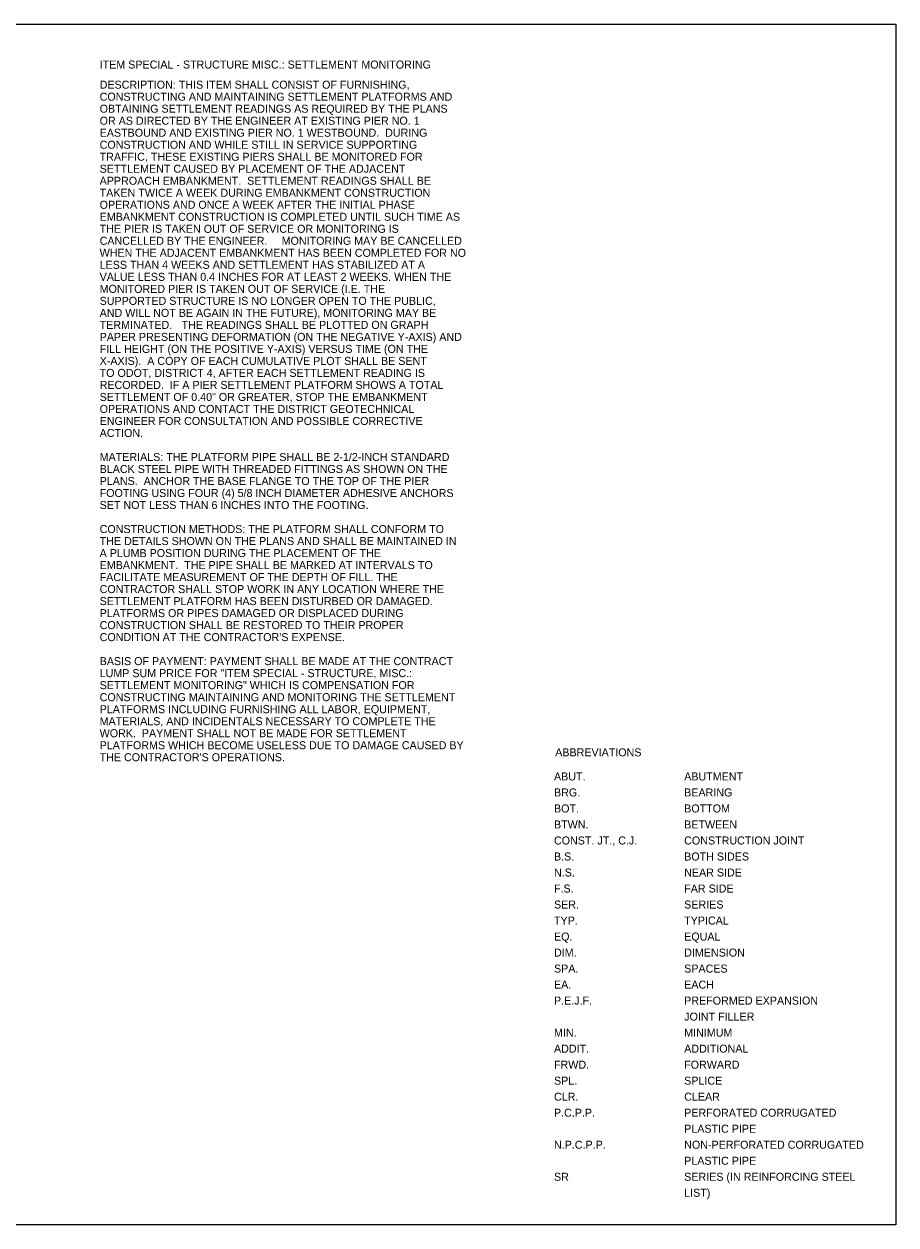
# Model space of a CAD drawing. Extents: x 1530552 to 1530730, y 675304 to 675366.
# Drawn here: x 1530669.97 to 1530685.22, y 675345.2 to 675366.2 of the extents above; entities that cross this region are included whole.
import ezdxf

# ---------------------------------------------------------------- set-up
doc = ezdxf.new("R2010")
doc.units = 0
doc.layers.add('BR_P_Gen_Text', color=7, linetype='Continuous')
doc.layers.add('Default', color=7, linetype='Continuous')

msp = doc.modelspace()

# ---------------------------------------------------------------- linework, layer by layer
at = {"layer": 'BR_P_Gen_Text'}
msp.add_lwpolyline([(1530654.722, 675366.197), (1530685.222, 675366.197), (1530685.222, 675345.197), (1530654.722, 675345.197)], close=True, dxfattribs=at)

# ---------------------------------------------------------------- texts
for s, p in [('ITEM SPECIAL - STRUCTURE MISC.: SETTLEMENT MONITORING', (1530671.295, 675365.418)), ('DESCRIPTION: THIS ITEM SHALL CONSIST OF FURNISHING, ', (1530671.295, 675365.066)), ('CONSTRUCTING AND MAINTAINING SETTLEMENT PLATFORMS AND ', (1530671.295, 675364.856)), ('OBTAINING SETTLEMENT READINGS AS REQUIRED BY THE PLANS ', (1530671.295, 675364.646)), ('OR AS DIRECTED BY THE ENGINEER AT EXISTING PIER NO. 1 ', (1530671.295, 675364.436)), ('EASTBOUND AND EXISTING PIER NO. 1 WESTBOUND.  DURING ', (1530671.295, 675364.226)), ('CONSTRUCTION AND WHILE STILL IN SERVICE SUPPORTING ', (1530671.295, 675364.016)), ('TRAFFIC, THESE EXISTING PIERS SHALL BE MONITORED FOR ', (1530671.295, 675363.806)), ('SETTLEMENT CAUSED BY PLACEMENT OF THE ADJACENT ', (1530671.295, 675363.596)), ('APPROACH EMBANKMENT.  SETTLEMENT READINGS SHALL BE ', (1530671.295, 675363.386)), ('TAKEN TWICE A WEEK DURING EMBANKMENT CONSTRUCTION ', (1530671.295, 675363.176)), ('OPERATIONS AND ONCE A WEEK AFTER THE INITIAL PHASE ', (1530671.295, 675362.966)), ('EMBANKMENT CONSTRUCTION IS COMPLETED UNTIL SUCH TIME AS ', (1530671.295, 675362.756)), ('THE PIER IS TAKEN OUT OF SERVICE OR MONITORING IS ', (1530671.295, 675362.546)), ('CANCELLED BY THE ENGINEER. ', (1530671.295, 675362.336)), ('MONITORING MAY BE CANCELLED ', (1530674.478, 675362.336)), ('WHEN THE ADJACENT EMBANKMENT HAS BEEN COMPLETED FOR NO ', (1530671.295, 675362.126)), ('LESS THAN 4 WEEKS AND SETTLEMENT HAS STABILIZED AT A ', (1530671.295, 675361.916)), ('VALUE LESS THAN 0.4 INCHES FOR AT LEAST 2 WEEKS. WHEN THE ', (1530671.295, 675361.706)), ('MONITORED PIER IS TAKEN OUT OF SERVICE (I.E. THE ', (1530671.295, 675361.496)), ('SUPPORTED STRUCTURE IS NO LONGER OPEN TO THE PUBLIC, ', (1530671.295, 675361.286)), ('AND WILL NOT BE AGAIN IN THE FUTURE), MONITORING MAY BE ', (1530671.295, 675361.076)), ('TERMINATED.', (1530671.295, 675360.866)), ('  THE READINGS SHALL BE PLOTTED ON GRAPH ', (1530672.624, 675360.866)), ('PAPER PRESENTING DEFORMATION (ON THE NEGATIVE Y-AXIS) AND ', (1530671.295, 675360.656)), ('FILL HEIGHT (ON THE POSITIVE Y-AXIS) VERSUS TIME (ON THE ', (1530671.295, 675360.446)), ('X-AXIS).  A COPY OF EACH CUMULATIVE PLOT SHALL BE SENT ', (1530671.295, 675360.236)), ('TO ODOT, DISTRICT 4, AFTER EACH SETTLEMENT READING IS ', (1530671.295, 675360.026)), ('RECORDED.  IF A PIER SETTLEMENT PLATFORM SHOWS A TOTAL ', (1530671.295, 675359.816)), ('SETTLEMENT OF 0.40" OR GREATER, STOP THE EMBANKMENT ', (1530671.295, 675359.606)), ('OPERATIONS AND CONTACT THE DISTRICT GEOTECHNICAL ', (1530671.295, 675359.396)), ('ENGINEER FOR CONSULTATION AND POSSIBLE CORRECTIVE ', (1530671.295, 675359.186)), ('ACTION.', (1530671.295, 675358.976)), ('MATERIALS: THE PLATFORM PIPE SHALL BE 2-1/2-INCH STANDARD ', (1530671.295, 675358.556)), ('BLACK STEEL PIPE WITH THREADED FITTINGS AS SHOWN ON THE ', (1530671.295, 675358.346)), ('PLANS.  ANCHOR THE BASE FLANGE TO THE TOP OF THE PIER ', (1530671.295, 675358.136)), ('FOOTING USING FOUR (4) 5/8 INCH DIAMETER ADHESIVE ANCHORS ', (1530671.295, 675357.926)), ('SET NOT LESS THAN 6 INCHES INTO THE FOOTING.', (1530671.295, 675357.716)), ('CONSTRUCTION METHODS: THE PLATFORM SHALL CONFORM TO ', (1530671.295, 675357.296)), ('THE DETAILS SHOWN ON THE PLANS AND SHALL BE MAINTAINED IN ', (1530671.295, 675357.086)), ('A PLUMB POSITION DURING THE PLACEMENT OF THE ', (1530671.295, 675356.876)), ('EMBANKMENT.  THE PIPE SHALL BE MARKED AT INTERVALS TO ', (1530671.295, 675356.666)), ('FACILITATE MEASUREMENT OF THE DEPTH OF FILL. THE ', (1530671.295, 675356.456)), ('CONTRACTOR SHALL STOP WORK IN ANY LOCATION WHERE THE ', (1530671.295, 675356.246)), ('SETTLEMENT PLATFORM HAS BEEN DISTURBED OR DAMAGED. ', (1530671.295, 675356.036)), ('PLATFORMS OR PIPES DAMAGED OR DISPLACED DURING ', (1530671.295, 675355.826)), ('CONSTRUCTION SHALL BE RESTORED TO THEIR PROPER ', (1530671.295, 675355.616)), ("CONDITION AT THE CONTRACTOR'S EXPENSE.", (1530671.295, 675355.406)), ('BASIS OF PAYMENT: PAYMENT SHALL BE MADE AT THE CONTRACT ', (1530671.295, 675354.986)), ('LUMP SUM PRICE FOR "ITEM SPECIAL - STRUCTURE, MISC.:  ', (1530671.295, 675354.776)), ('SETTLEMENT MONITORING" WHICH IS COMPENSATION FOR ', (1530671.295, 675354.566)), ('CONSTRUCTING MAINTAINING AND MONITORING THE SETTLEMENT ', (1530671.295, 675354.356)), ('PLATFORMS INCLUDING FURNISHING ALL LABOR, EQUIPMENT, ', (1530671.295, 675354.146)), ('MATERIALS, AND INCIDENTALS NECESSARY TO COMPLETE THE ', (1530671.295, 675353.936)), ('WORK.  PAYMENT SHALL NOT BE MADE FOR SETTLEMENT ', (1530671.295, 675353.726)), ('PLATFORMS WHICH BECOME USELESS DUE TO DAMAGE CAUSED BY ', (1530671.295, 675353.516)), ("THE CONTRACTOR'S OPERATIONS.", (1530671.295, 675353.306))]:
    msp.add_text(s, height=0.14, dxfattribs=at).set_placement(p)
at = {"layer": 'Default'}
for s, p in [('ABBREVIATIONS', (1530679.262, 675353.391)), ('ABUT.', (1530679.241, 675352.97)), ('ABUTMENT', (1530681.518, 675352.97)), ('BRG.', (1530679.241, 675352.69)), ('BEARING', (1530681.518, 675352.69)), ('BOT.', (1530679.241, 675352.41)), ('BOTTOM', (1530681.518, 675352.41)), ('BTWN.', (1530679.241, 675352.13)), ('BETWEEN', (1530681.518, 675352.13)), ('CONST. JT., C.J.', (1530679.241, 675351.85)), ('CONSTRUCTION JOINT', (1530681.518, 675351.85)), ('B.S.', (1530679.241, 675351.57)), ('BOTH SIDES', (1530681.518, 675351.57)), ('N.S.', (1530679.241, 675351.29)), ('NEAR SIDE', (1530681.518, 675351.29)), ('F.S.', (1530679.241, 675351.01)), ('FAR SIDE', (1530681.518, 675351.01)), ('SER.', (1530679.241, 675350.73)), ('SERIES', (1530681.518, 675350.73)), ('TYP.', (1530679.241, 675350.45)), ('TYPICAL', (1530681.518, 675350.45)), ('EQ.', (1530679.241, 675350.17)), ('EQUAL', (1530681.518, 675350.17)), ('DIM.', (1530679.241, 675349.89)), ('DIMENSION', (1530681.518, 675349.89)), ('SPA.', (1530679.241, 675349.61)), ('SPACES', (1530681.518, 675349.61)), ('EA.', (1530679.241, 675349.33)), ('EACH', (1530681.518, 675349.33)), ('P.E.J.F.', (1530679.241, 675349.05)), ('PREFORMED EXPANSION ', (1530681.518, 675349.05)), ('JOINT FILLER', (1530681.518, 675348.77)), ('MIN.', (1530679.241, 675348.49)), ('MINIMUM', (1530681.518, 675348.49)), ('ADDIT.', (1530679.241, 675348.21)), ('ADDITIONAL', (1530681.518, 675348.21)), ('FRWD.', (1530679.241, 675347.93)), ('FORWARD', (1530681.518, 675347.93)), ('SPL.', (1530679.241, 675347.65)), ('SPLICE', (1530681.518, 675347.65)), ('CLR.', (1530679.241, 675347.37)), ('CLEAR', (1530681.518, 675347.37)), ('P.C.P.P.', (1530679.241, 675347.09)), ('PERFORATED CORRUGATED', (1530681.518, 675347.09)), ('PLASTIC PIPE', (1530681.518, 675346.81)), ('N.P.C.P.P.', (1530679.241, 675346.53)), ('NON-PERFORATED CORRUGATED', (1530681.518, 675346.53)), ('PLASTIC PIPE', (1530681.518, 675346.25)), ('SR', (1530679.241, 675345.97)), ('SERIES (IN REINFORCING STEEL', (1530681.518, 675345.97)), ('LIST)', (1530681.518, 675345.69))]:
    msp.add_text(s, height=0.14, dxfattribs=at).set_placement(p)

doc.saveas('drawing.dxf')
